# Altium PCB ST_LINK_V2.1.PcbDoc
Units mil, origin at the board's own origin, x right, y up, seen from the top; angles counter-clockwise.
Board outline 1520 x 655 mil, 2 copper layers (Top Layer, Bottom Layer); 55 components, 47 nets, 188 pads, 66 vias.
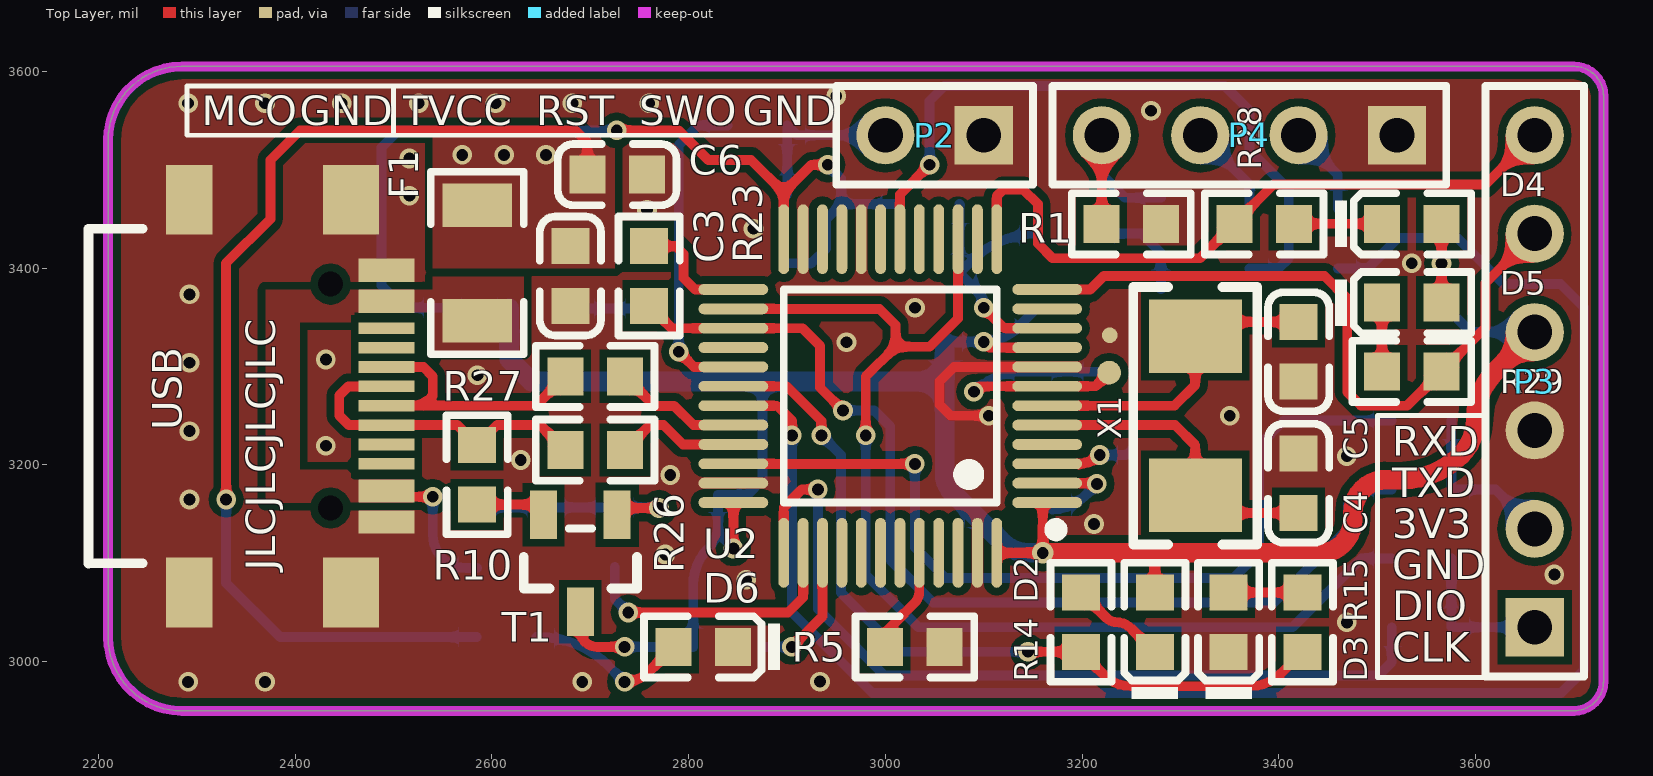
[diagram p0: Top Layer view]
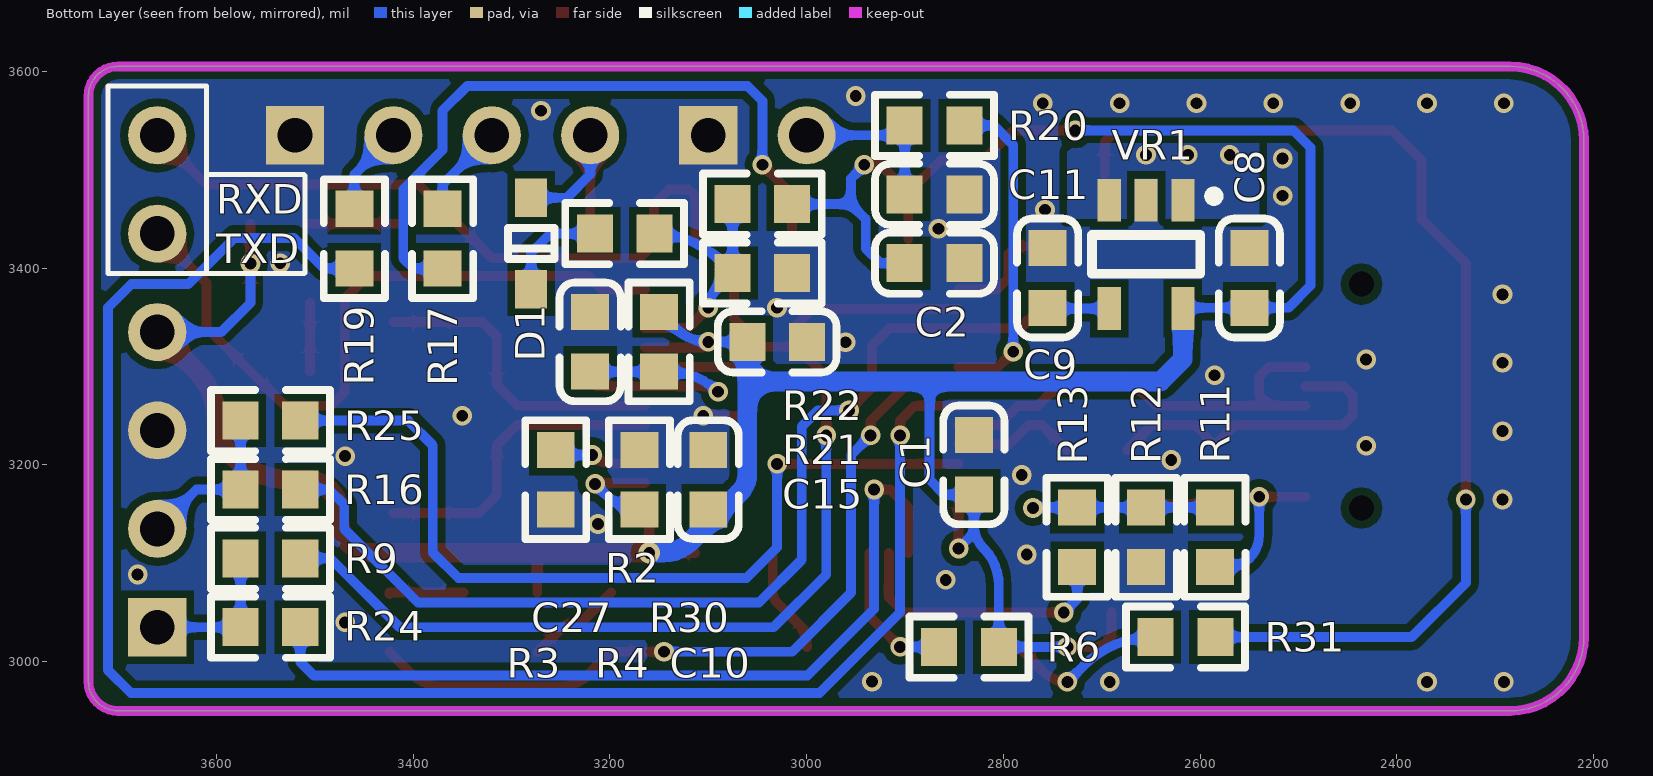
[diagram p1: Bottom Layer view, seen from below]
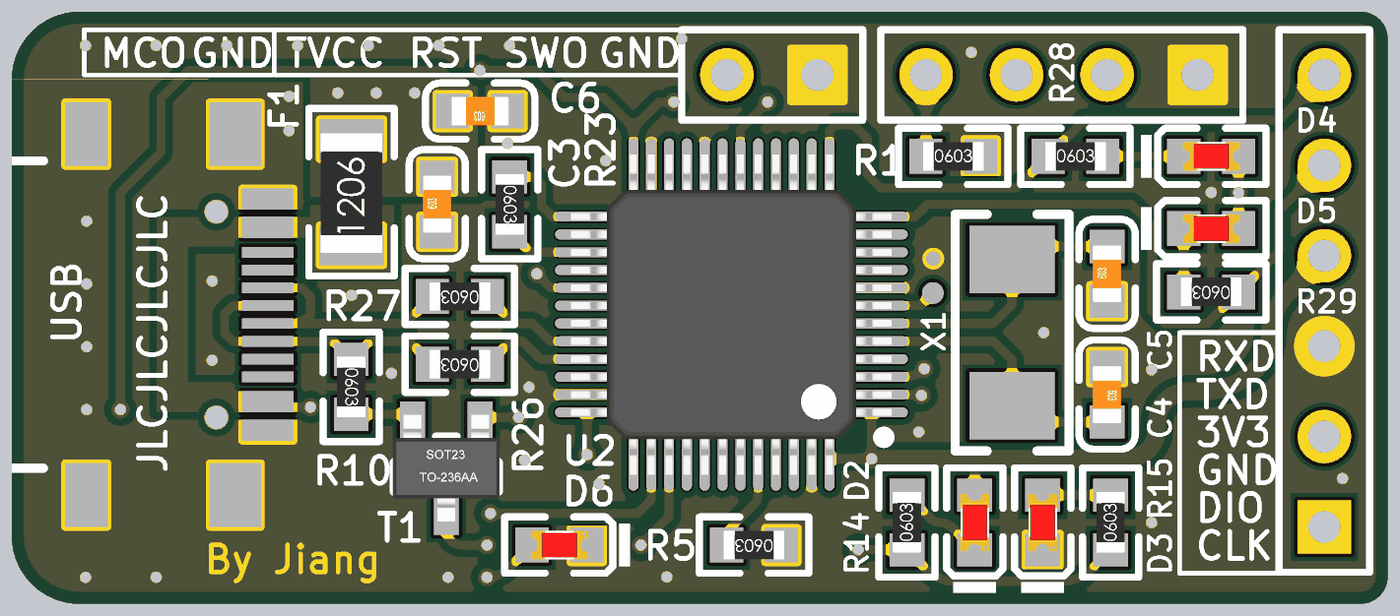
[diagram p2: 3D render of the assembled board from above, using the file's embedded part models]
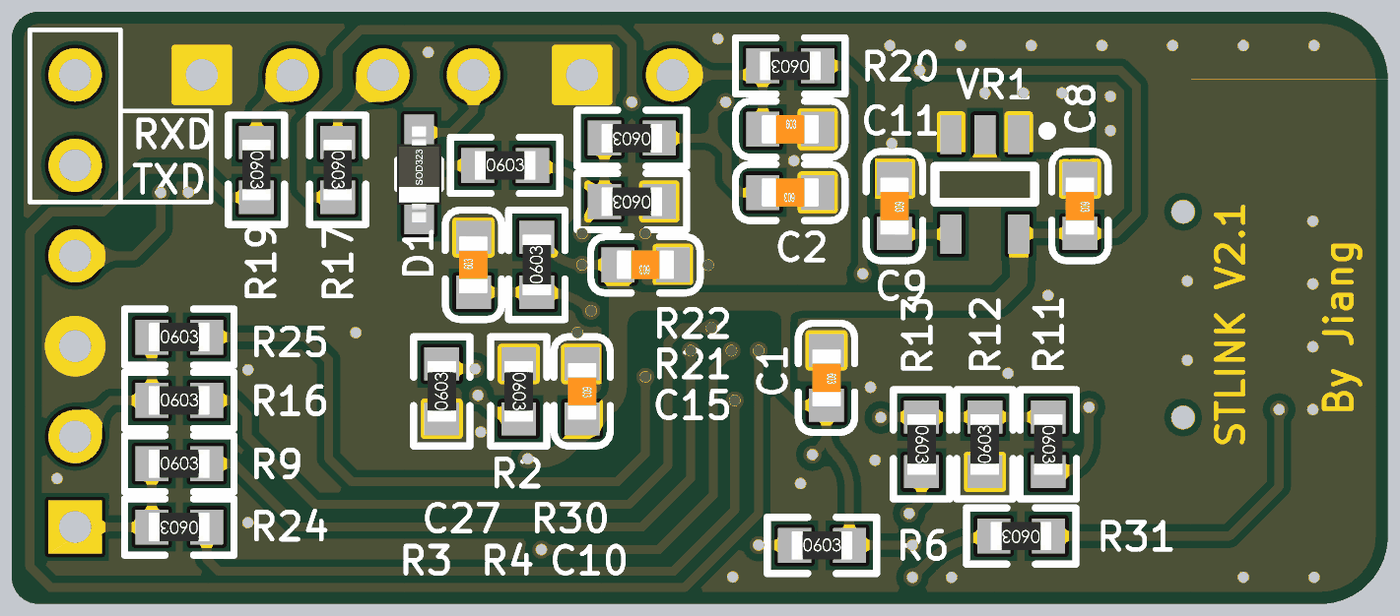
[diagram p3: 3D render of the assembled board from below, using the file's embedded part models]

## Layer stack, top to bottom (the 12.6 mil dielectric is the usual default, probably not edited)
Top Solder: solder mask 0.4, Solder Resist, Dk 3.5
Top Layer: signal copper 1.4
Dielectric 1: dielectric 12.6, FR-4, Dk 4.8
Bottom Layer: signal copper 1.4
Bottom Solder: solder mask 0.4, Solder Resist, Dk 3.5

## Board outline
2285,2950 cw(c2285,3025) 2210,3025 2210,3530 cw(c2285,3530) 2285,3605 3700,3605 cw(c3700,3575) 3730,3575 3730,2980 cw(c3700,2980) 3700,2950

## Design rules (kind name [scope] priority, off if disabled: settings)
Clearance [All] p1: gap=8 ignorepadtopadclearanceinfootprint=TRUE except(0: Arc-Hole Track-Hole SMDPad-Hole THPad-Hole Via-Hole Fill-Hole Poly-Hole Region-Hole Text-Hole)
PolygonConnect PolygonConnect_8 [All vs IsNamedPolygon('Top Layer-5V_USB_CHG 1') Or  IsNamedPolygon('Top Layer-5V_USB_CHG') Or  IsNamedPolygon('Bottom Layer-5V_USB_CHG') Or  IsNamedPolygon('Bottom Layer-GND') Or  IsNamedPolygon('Top Layer-GND') Or  IsNamedPolygon('Top Layer-5V_USB_CHG 2')] p1: connectstyle=Direct reliefconductorwidth=10 reliefentries=4 polygonreliefangle="90 Angle" airgapwidth=10
PolygonConnect PolygonConnect_7 [All vs IsNamedPolygon('Top Layer-5V_USB_CHG 2')] p2: connectstyle=Direct reliefconductorwidth=10 reliefentries=4 polygonreliefangle="90 Angle" airgapwidth=10
PolygonConnect PolygonConnect_6 [All vs IsNamedPolygon('Top Layer-5V_USB_CHG 1')] p3: connectstyle=Direct reliefconductorwidth=10 reliefentries=4 polygonreliefangle="90 Angle" airgapwidth=10
PolygonConnect PolygonConnect_5 [All vs IsNamedPolygon('Top Layer-No Net') Or  IsNamedPolygon('Top Layer-5V_USB_CHG') Or  IsNamedPolygon('Bottom Layer-No Net') Or  IsNamedPolygon('Bottom Layer-5V_USB_CHG') Or  IsNamedPolygon('Top Layer-5V_USB_CHG 2')] p4: connectstyle=Direct reliefconductorwidth=10 reliefentries=4 polygonreliefangle="90 Angle" airgapwidth=10
PolygonConnect PolygonConnect_4 [All vs IsNamedPolygon('Top Layer-5V_USB_CHG 2')] p5: connectstyle=Direct reliefconductorwidth=10 reliefentries=4 polygonreliefangle="90 Angle" airgapwidth=10
PolygonConnect PolygonConnect_3 [All vs IsNamedPolygon('Top Layer-5V_USB_CHG 1') Or  IsNamedPolygon('Top Layer-5V_USB_CHG') Or  IsNamedPolygon('Bottom Layer-5V_USB_CHG')] p6: connectstyle=Direct reliefconductorwidth=10 reliefentries=4 polygonreliefangle="90 Angle" airgapwidth=10
PolygonConnect PolygonConnect_2 [All vs IsNamedPolygon('Top Layer-5V_USB_CHG') Or  IsNamedPolygon('Top Layer-5V_USB_CHG 1')] p7: connectstyle=Direct reliefconductorwidth=10 reliefentries=4 polygonreliefangle="90 Angle" airgapwidth=10
PolygonConnect PolygonConnect_1 [All vs IsNamedPolygon('Top Layer-5V_USB_CHG 1') Or  IsNamedPolygon('Top Layer-5V_USB_CHG')] p8: connectstyle=Direct reliefconductorwidth=10 reliefentries=4 polygonreliefangle="90 Angle" airgapwidth=10
PolygonConnect [All] p9: connectstyle=Relief reliefconductorwidth=10 reliefentries=4 polygonreliefangle="90 Angle" airgapwidth=10
RoutingVias [All] p1: holewidth=12 width=20 viastyle="Through Hole" minholewidth=12 minwidth=18 maxholewidth=28 maxwidth=50
SilkToSilkClearance [All] p1: silktosilkclearance=5
SilkToSolderMaskClearance [IsPad] p1: minsilkscreentomaskgap=5 clearancetoexposedcopper=TRUE
SolderMaskExpansion [All] p1: expansion=4
Width [All] p1: maxlimit=50 minlimit=10 preferedwidth=10
28 further rules are at their usual default settings.

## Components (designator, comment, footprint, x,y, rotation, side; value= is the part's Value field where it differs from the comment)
C1 "Capacitor" 0603_C 2830,3200 r270 bottom value=100nF
C2 "Capacitor" 0603_C 2870,3405 r0 bottom value=100nF
C3 "104" 0603_C 2679.96,3391.97 r90 top
C4 "Capacitor" 0603_C 3420,3181.42 r270 top value=20pF
C5 "Capacitor" 0603_C 3420,3315 r90 top value=20pF
C6 "104" 0603_C 2727.4,3495 r180 top
C8 "104" 0603_C 2550,3390 r270 bottom
C9 "104" 0603_C 2755,3390 r270 bottom
C10 "Capacitor" 0603_C 3100,3185 r270 bottom value=100nF
C11 "20pF" 0603_C 2870,3475 r180 bottom
C15 "Capacitor" 0603_C 3030,3325 r0 bottom value=100nF
C27 "Capacitor" 0603_C 3220,3325 r90 bottom value=103
D1 "BAT60JFILM" SOD-323 3280,3425 r90 bottom
D2 "绿灯 0603" 0603_LED_S1 3273.86,3040 r90 top
D3 "红灯 0603" 0603_LED_S1 3348.86,3040 r90 top
D4 "红灯 0603" 0603_LED_S1 3535,3445 r0 top
D5 "红灯 0603" 0603_LED_S1 3535,3365 r0 top
D6 "红灯 0603" 0603_LED_S1 2815,3015 r180 top
F1 "Fuse 2" 1206_R 2585.31,3405.22 r90 top
P2 "Header 2" HDR1X2 3100,3535 r180 top
P3 "Header 6" HDR1X6 3660,3035 r90 top
P4 "Header 4" HDR1X4 3520,3535 r180 top
R1 "Resistor" 0603_R 3250,3445 r0 top value=10K
R2 "100R" 0603_R 3185,3435 r180 bottom value=22R
R3 "N/A" 0603_R 3255,3185 r90 bottom value=10K
R4 "Resistor" 0603_R 3170,3185 r270 bottom value=10K
R5 "Resistor" 0603_R 3030,3015 r180 top value=100K
R6 "Resistor" 0603_R 2835,3014.69 r180 bottom value=4.7K
R9 "Resistor" 0603_R 3545,3105 r180 bottom value=22R
R10 "Resistor" 0603_R 2585,3190 r270 top value=1K5
R11 "Resistor" 0603_R 2585,3126.42 r270 bottom value=10K
R12 "Resistor" 0603_R 2655,3126.42 r90 bottom value=36K
R13 "Resistor" 0603_R 2725,3126.42 r270 bottom value=100R
R14 "Resistor" 0603_R 3198.86,3040 r90 top value=330R
R15 "Resistor" 0603_R 3423.86,3040 r90 top value=330R
R16 "Resistor" 0603_R 3545,3175 r180 bottom value=22R
R17 "Resistor" 0603_R 3370,3430 r270 bottom value=22R
R19 "Resistor" 0603_R 3459.74,3430 r270 bottom value=22R
R20 "Resistor" 0603_R 2870,3545 r0 bottom value=100R
R21 "Resistor" 0603_R 3045,3395 r0 bottom value=4K7
R22 "Resistor" 0603_R 3045,3465 r0 bottom value=4K7
R23 "Resistor" 0603_R 2760,3391.97 r270 top value=100R
R24 "Resistor" 0603_R 3545,3035 r0 bottom value=0R
R25 "Resistor" 0603_R 3545,3245 r180 bottom value=0R
R26 "Resistor" 0603_R 2705,3215 r180 top value=10R
R27 "Resistor" 0603_R 2705,3290 r180 top value=10R
R28 "Resistor" 0603_R 3385,3445 r0 top value=1K
R29 "Resistor" 0603_R 3535,3295 r180 top value=1K
R30 "Resistor" 0603_R 3150,3325 r90 bottom value=10K
R31 "Resistor" 0603_R 2615,3025 r0 bottom value=1K
T1 "9013-SOT23" SOT-23(SOT-23-3) 2690,3100 r90 top
U2 "STM32F103CBT6" LQFP-48_7x7x05P 3005,3270 r90 top locked
USB "TYPE-C 12P" "TYPE-C 12P 贴片" 2190,3440 r270 top locked
VR1 "SPX3819M5-L-3-3" SOT-23-5 2655,3414.02 r90 bottom
X1 "XTAL_8M_NX3225GD" SMD-5032_2P 3315,3250 r90 top value=8.00Mhz

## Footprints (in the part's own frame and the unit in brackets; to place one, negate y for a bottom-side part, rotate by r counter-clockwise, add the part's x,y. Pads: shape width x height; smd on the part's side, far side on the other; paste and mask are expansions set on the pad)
0603_C [mm]
  rect 0.93x0.98 smd: 1(-0.77,0) 2(0.77,0)
  silkscreen extent -1.53,-0.79 1.54,0.79, body extent -0.8,-0.4 0.8,0.4, height 0.3
0603_LED_S1 [mm]
  rect 0.93x0.98 smd: A(0.77,0) K(-0.77,0)
  silkscreen extent -1.98,-0.79 1.54,0.79, body extent -0.8,-0.4 0.8,0.4, height 0.6
0603_R [mm]
  rect 0.93x0.98 smd: 1(-0.77,0) 2(0.77,0)
  silkscreen extent -1.53,-0.79 1.54,0.79, body extent -0.85,-0.4 0.85,0.4, height 0.56
1206_R [mm]
  rect 1.13x1.8 smd: 1(-1.49,0) 2(1.49,0)
  silkscreen extent -2.36,-1.2 2.35,1.2, body extent -1.7,-0.86 1.65,0.87, height 0.85
HDR1X2 [mm] "Connector; Header; 2 Position"
  rect 1.5x1.5 hole 0.9: 1(0,0)
  round 1.5 hole 0.9: 2(2.54,0)
  silkscreen extent -1.27,-1.27 3.81,1.27
HDR1X4 [mm] "Connector; Header; 4 Position"
  rect 1.5x1.5 hole 0.9: 1(0,0)
  round 1.5 hole 0.9: 2(2.54,0) 3(5.08,0) 4(7.62,0)
  silkscreen extent -1.27,-1.27 8.89,1.27
HDR1X6 [mm] "Connector; Header; 6 Position"
  rect 1.5x1.5 hole 0.9: 1(0,0)
  round 1.5 hole 0.9: 2(2.54,0) 3(5.08,0) 4(7.62,0) 5(10.16,0) 6(12.7,0)
  silkscreen extent -1.27,-1.27 13.97,1.27
LQFP-48_7x7x05P [mm]
  oval 0.28x1.8 smd mask+0.051: 1(-2.75,-4.05) 2(-2.25,-4.05) 3(-1.75,-4.05) 4(-1.25,-4.05) 5(-0.75,-4.05) 6(-0.25,-4.05) 7(0.25,-4.05) 8(0.75,-4.05) 9(1.25,-4.05) 10(1.75,-4.05) 11(2.25,-4.05) 12(2.75,-4.05) 25(2.75,4.05) 26(2.25,4.05) 27(1.75,4.05) 28(1.25,4.05) 29(0.75,4.05) 30(0.25,4.05) 31(-0.25,4.05) 32(-0.75,4.05) 33(-1.25,4.05) 34(-1.75,4.05) 35(-2.25,4.05) 36(-2.75,4.05)
  oval 1.8x0.28 smd mask+0.051: 13(4.05,-2.75) 14(4.05,-2.25) 15(4.05,-1.75) 16(4.05,-1.25) 17(4.05,-0.75) 18(4.05,-0.25) 19(4.05,0.25) 20(4.05,0.75) 21(4.05,1.25) 22(4.05,1.75) 23(4.05,2.25) 24(4.05,2.75) 37(-4.05,2.75) 38(-4.05,2.25) 39(-4.05,1.75) 40(-4.05,1.25) 41(-4.05,0.75) 42(-4.05,0.25) 43(-4.05,-0.25) 44(-4.05,-0.75) 45(-4.05,-1.25) 46(-4.05,-1.75) 47(-4.05,-2.25) 48(-4.05,-2.75)
  silkscreen extent -3.6,-4.42 2.75,2.75, body extent -4.5,-4.5 4.5,4.5, height 1.6
SMD-5032_2P [mm]
  rect 1.9x2.4 smd: 1(-2.05,0) 2(2.05,0)
  silkscreen extent -3.32,-1.6 3.32,1.6
SOD-323 [mm]
  rect 1x0.83 smd: 1(1.18,0) 2(-1.18,0)
  silkscreen extent -0.4,-0.6 0.4,0.6, body extent -1.35,-0.63 1.35,0.63, height 1.1
SOT-23(SOT-23-3) [mm]
  rect 1.25x0.7 smd: 1(1.25,-0.95) 2(1.25,0.95) 3(-1.25,0)
  silkscreen extent -0.65,-1.46 0.9,1.46, body extent -1.5,-1.5 1.5,1.5, height 1.3
SOT-23-5 [mm]
  rect 1.1x0.6 smd: 1(1.4,-0.95) 2(1.4,0) 3(1.4,0.95) 4(-1.4,0.95) 5(-1.4,-0.95)
  silkscreen extent -0.5,-1.87 1.62,1.4
"TYPE-C 12P 贴片" [mm]
  rect 1.8x1.45 smd: 0(-0.75,6.78) 0(9.39,6.78)
  rect 1.8x1.2 smd: 0(-0.75,2.6) 0(9.39,2.6)
  round 0 hole 0.65: 5(1.43,6.25) 5(7.21,6.25)
  rect 0.3x1.45 smd: A1(0.92,7.695) A4(1.72,7.695) A5(3.07,7.695) A6(4.07,7.695) A7(4.57,7.695) A8(5.57,7.695) A9(6.92,7.695) A12(7.72,7.695) B1(7.42,7.695) B4(6.62,7.695) B5(6.07,7.695) B6(5.07,7.695) B7(3.57,7.695) B8(2.57,7.695) B9(2.02,7.695) B12(1.22,7.695)
  silkscreen extent 0,0 8.64,1.4, body extent 0,0 8.64,8, height 3.21

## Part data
C1 C2 C10 C15 C27: library part MCD-00211, "Capacitor, MLCC, 100nF, 16V, X7R, 10%, 0603, T=0,8mm", Manufacturer=YAGEO, Manufacturer_Part_Number=CC0603KRX7R7BB104, Package=C0603
C3 C6 C8 C9: library part "0603 2.7pF (2R7) 0.25pF 50V", "贴片电容", Package=0603, SuppliersPartNumber=C16149
C4 C5: library part MCD-00637, "Capacitor, MLCC, 10pF, 50V, NPO, 5%, 0603, T=0,8mm", Manufacturer=YAGEO, Manufacturer_Part_Number=CC0603JRNPO9BN100, Package=C0603
C11: library part MCD-00638, "Capacitor, MLCC, 20pF, 50V, NPO, 5%, 0603, T=0,8mm", Manufacturer=YAGEO, Manufacturer_Part_Number=CC0603JRNPO9BN200, Package=C0603
D1: library part MCD-00034, Manufacturer=STMICROELECTRONICS
D2: library part "0603 绿灯", "发光二极管", Package=0603, SuppliersPartNumber=C72043
D3 D4 D5 D6: library part "0603 红灯", "发光二极管", Package=0603, SuppliersPartNumber=C2286
F1: "Fuse"
P2: "Header, 2-Pin"
P3: "Header, 6-Pin"
P4: "Header, 4-Pin"
R1 R3 R4 R11: library part MCD-00220, "Resistor,10K,0603,1%,1/10W", Manufacturer=YAGEO, Manufacturer_Part_Number=RC0603FR-0710KL, Package=R0603
R2 R9 R16 R17 R19 R24 R25: library part MCD-00066, "Resistor,22R,0603,1%,1/10W", Manufacturer=YAGEO, Manufacturer_Part_Number=RC0603FR-0722RL, Package=R0603
R5 R30: library part MCD-00223, "Resistor,100K,0603,1%,1/10W", Manufacturer=YAGEO, Manufacturer_Part_Number=RC0603FR-07100KL, Package=R0603
R6 R14 R15 R28 R29 R31: library part MCD-00197, "Resistor,330R,0603,1%,1/10W", Manufacturer=YAGEO, Manufacturer_Part_Number=RC0603FR-07330RL, Package=R0603
R10: library part MCD-00217, "Resistor,1K5,0603,1%,1/10W", Manufacturer=YAGEO, Manufacturer_Part_Number=RC0603FR-071K5L, Package=R0603
R12: library part MCD-00221, "Resistor,36K,0603,1%,1/10W", Manufacturer=YAGEO, Manufacturer_Part_Number=RC0603FR-0736KL, Package=R0603
R13 R20 R23 R26 R27: library part MCD-00224, "Resistor,100R,0603,1%,1/10W", Manufacturer=YAGEO, Manufacturer_Part_Number=RC0603FR-07100RL, Package=R0603
R21 R22: library part MCD-00219, "Resistor,4K7,0603,1%,1/10W", Manufacturer=YAGEO, Manufacturer_Part_Number=RC0603FR-074K7L, Package=R0603
T1: library part MCD-00073, "NPN Bipolar Transistor", Manufacturer=NXP, Manufacturer_Part_Number=BSR14
U2: library part MCD-00085, "Medium-density performance line ARM-based 32-bit MCU with 128KB Flash", Manufacturer=STMICROELECTRONICS
VR1: "LDO"
X1: library part MCD-00092, "Crystal 8Mhz, 8pF, -+50PPM, SMD", Manufacturer=NDK, Manufacturer_Part_Number="NX3225GD 8MHz EXS00A-CG04874"

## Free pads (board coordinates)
  round 24 smd: 9(3227.46,3293.78)
  round 16 smd: 10(3227.98,3331.84)

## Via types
v1: diameter 20, hole 12, Top Layer to Bottom Layer, tented both sides, 65 vias
v2: diameter 22, hole 12, Top Layer to Bottom Layer, tented both sides, 1 vias

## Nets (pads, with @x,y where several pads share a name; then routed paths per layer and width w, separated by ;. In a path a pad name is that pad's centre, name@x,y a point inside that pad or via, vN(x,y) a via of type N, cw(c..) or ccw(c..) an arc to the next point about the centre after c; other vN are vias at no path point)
3V3_STLK: C1.2 C2.2 C8.2 C10.2 C15.2 D2.A D4.A D5.A P3.4 R6.2 R22.1 R30.2 T1.3 U2.1 U2.9 U2.24 U2.36 U2.48 VR1.5 | length 3500
  Top Layer w10: T1.3 2690,3032.07 ccw(c2707.07,3032.07) 2695,3020 ccw(c2707.07,3032.07) 2707.07,3015 v1(2735,3015) ; v1(2727,3540) 2790,3540 2820,3510 2863.46,3510 2896.73,3476.73 ; v1(2845.55,3115.08) U2.36 ; U2.24 2896.73,3476.73 ; v1(2941.37,3505) 2925,3505 2896.73,3476.73 ; v1(3100,3325) 3105.79,3319.21 U2.9 ; U2.48 v2(3160,3110.55) 3160,3161.73 U2.1 ; D2.A 3273.86,3110.55 ; D5.A v1(3565.31,3404.69) D4.A
  Top Layer w20: v2(3160,3110.55) 3273.86,3110.55 3442.19,3110.55 ccw(c3442.19,3142.81) 3465,3120 ccw(c3440.86,3144.14) 3475,3144.14 3475,3150.86 cw(c3509.14,3150.86) 3485,3175 cw(c3509.14,3150.86) 3509.14,3185 3524.64,3185 ccw(c3524.64,3270.36) 3585,3210 ccw(c3548.79,3246.21) 3600,3246.21 cw(c3669.5,3246.21) 3620.36,3295.36 P3.4
  Bottom Layer w10: VR1.5 ccw(c2615.7,3357) 2615.7,3359.69 C8.2 2510.39,3359.69 2487.75,3382.32 2487.75,3522.68 2505.07,3540 v1(2727,3540) ; v1(2735,3015) 2804.37,3015 R6.2 2804.68,3078.03 cw(c2856.97,3078.03) 2820,3115 ccw(c2795.86,3139.14) 2830,3139.14 ; v1(2845.55,3115.08) 2836.02,3124.61 cw(c2850.55,3139.14) 2830,3139.14 ; 2875,3284.69 2875,3185 2859.69,3169.69 C1.2 2830,3139.14 ; C2.2 2925,3405 2940,3420 2940,3450 2955,3465 ; v1(2941.37,3505) 2941.37,3504.7 2955,3491.07 2955,3465 ; R22.1 2955,3465 ; C15.2 v1(3100,3325) ccw(c3100,3372.52) 3133.6,3338.92 R30.2 ; v1(3565.31,3404.69) 3565.31,3364.69 3595,3335 P3.4
  Bottom Layer w20: VR1.5 2617.6,3307.4 2640.31,3284.69 2875,3284.69 3060.31,3284.69 ; C15.2 3060.31,3284.69 ; 3068.5,3171.19 cw(c3088.25,3190.94) 3060.31,3190.94 3060.31,3284.69 ; 3068.5,3171.56 3117.65,3122.41 ccw(c3146.28,3151.04) 3146.28,3110.55 v2(3160,3110.55)
5V_USB_CHG: F1.1 R11.2 USB.A4 USB.A9 USB.B4 USB.B9 | length 149.9
  Top Layer w10: USB.A9 v1(2540,3167.56)
  Bottom Layer w10: v1(2540,3167.56) 2540,3129.14 ccw(c2574.14,3129.14) 2550,3105 ccw(c2573.76,3128.76) 2573.76,3095.16 R11.2@2585,3095.16
AIN_1: R2.2 R21.2 R22.2 U2.10 | length 280.3
  Top Layer w10: v1(3100,3359.68) 3120.79,3338.9 U2.10
  Bottom Layer w10: R22.2@3076.03,3464.29 R22.2 R21.2 ; v1(3100,3359.68) ccw(c3074.34,3359.68) 3092.48,3377.83 R21.2 ; R2.2 ccw(c3154.68,3339.95) 3087.48,3407.16 R21.2
GND: C1.1 C2.1 C3.1 C4.1 C5.1 C6.1 C8.1 C9.1 C10.1 C11.2 C15.1 C27.2 D3.K D6.K P2.1 P3.3 P4.1 pad.10 R1.2 R3.1 R4.1 R5.1 R12.1 R21.1 U2.8 U2.20 U2.23 U2.35 U2.47 USB.0 USB.A1 USB.A12 USB.B1 USB.B12 VR1.2 | length 193.7
  Top Layer w10: v1(3105,3250) 3066.21,3250 3055,3261.21 3055,3284.69 3069.84,3299.53 U2.8
  other v1: 2291.36,2979.43 2369.47,2979.43 2691.89,2979.43 2933.61,2979.69 3469.11,3039.9 2858.65,3083.1 3680,3088.58 2776.36,3108.9 3212,3140 2292.72,3164.85 2781.36,3189.69 2629.48,3204.97 3469.11,3208.9 2431.36,3219.42 2292.72,3234.33 3350,3250 2585.31,3291.19 2292.72,3303.81 2431.36,3307.09 2960.57,3324.69 3030.19,3359.68 2292.72,3373.29 3535,3405 2865.99,3440.02 2757.72,3459.37 2516.26,3473.46 2516.26,3511.32 3270,3560 2291.36,3567.47 2369.47,3567.47 2447.57,3567.47 2525.68,3567.47 2603.79,3567.47 2681.89,3567.47 2760,3567.47 2950,3575
LED_STLK: R14.1 R15.1 U2.30 | length 806
  Top Layer w10: U2.30 2899.84,3279.84 2935,3244.69 v1(2935,3230) ; v1(3145,3010) 3198.54,3010 R14.1 3222.21,2986.34 ccw(c3249.58,3013.71) 3249.58,2975 3370.86,2975 ccw(c3370.86,3019.22) 3402.12,2987.95 R15.1
  Bottom Layer w10: v1(2935,3230) 2955,3210 2955,3070 3015,3010 v1(3145,3010)
MCO: C11.1 P2.2 R20.2 | length 173.8
  Bottom Layer w10: C11.1 R20.2 2910.32,3535 P2.2
NetC3_2: C3.2 C6.2 F1.2 R31.1 VR1.1 VR1.3 | length 1098.5
  Top Layer w10: v1(2330,3164.85) 2330,3405 2375,3450 2375,3510 2405,3540 2685,3540 2697.09,3527.91 C6.2
  Bottom Layer w10: v1(2330,3164.85) 2330,3080 2385,3025 R31.1
  other v1: 2570,3515.07 2612.5,3515.07 2655,3515.07
NetC9_2: C9.2 VR1.4 | length 62.8
  Bottom Layer w10: VR1.4 2753.1,3358.9 ccw(c2753.1,3361.59) C9.2
NetD1_2: D1.2 R2.1 | length 109.6
  Bottom Layer w10: R2.1 3260.31,3435 3280,3415.32 D1.2
NetD2_K: D2.K R14.2 | length 98.6
  Top Layer w10: R14.2 3225.05,3044.12 ccw(c3235,3054.07) 3235,3040 cw(c3235,3019.37) 3249.58,3033.97 D2.K
NetD3_A: D3.A R15.2 | length 76.5
  Top Layer w10: D3.A R15.2 R15.2@3423.86,3068.86
NetD4_K: D4.K R28.2 | length 89.4
  Top Layer w10: R28.2 D4.K
NetD5_K: D5.K R29.2 | length 70
  Top Layer w10: R29.2 D5.K
NetD6_A: D6.A R31.2 | length 167.2
  Top Layer w10: v1(2735,2979.43) ccw(c2735,3013.51) 2759.1,2989.41 D6.A
  Bottom Layer w10: R31.2 2648.01,3025 cw(c2648.01,2925) 2718.72,2995.71 v1(2735,2979.43)
NetP3_1: P3.1 R9.1 R24.2 | length 154.7
  Bottom Layer w10: R9.1 R24.2 P3.1
NetP3_2: P3.2 R16.1 R25.1 | length 171.3
  Bottom Layer w10: R25.1 R16.1 3620,3175 P3.2
NetP4_2: P4.2 R19.1 | length 91.1
  Bottom Layer w10: P4.2 3459.74,3495.26 R19.1
NetP4_3: P4.3 R17.1 | length 95.4
  Bottom Layer w10: P4.3 3370,3485 R17.1
NetR3_2: R3.2 U2.3 | length 90.1
  Top Layer w10: U2.3 3196.52,3201.1 ccw(c3196.52,3231.48) v1(3218,3210)
  Bottom Layer w10: v1(3218,3210) 3244.68,3210 R3.2@3250,3215.32
NetR4_2: R4.2 U2.2 | length 104.5
  Top Layer w10: U2.2 3213.29,3181.42 cw(c3213.29,3179) v1(3215,3180.71)
  Bottom Layer w10: R4.2 ccw(c3170,3200.5) 3202.39,3168.1 v1(3215,3180.71)
NetR5_2: R5.2 U2.44 | length 107.8
  Top Layer w10: R5.2 cw(c3035.14,3015) 3010.07,3040.07 3030,3060 ccw(c3019.07,3070.93) 3034.53,3070.93 U2.44
NetR6_1: R6.1 U2.39 | length 133.4
  Top Layer w10: v1(2905,3015) 2936.1,3046.1 U2.39
  Bottom Layer w10: R6.1@2880.31,3015 2880.63,3014.69 2880.94,3015 v1(2905,3015)
NetR10_2: R10.2 T1.2 | length 71.9
  Top Layer w10: R10.2 2642.13,3159.68 T1.2
NetR11_1: R11.1 R12.2 R13.1 T1.1 | length 231
  Top Layer w10: T1.1 2734.33,3156.14 v1(2770,3156.14)
  Bottom Layer w10: R11.1 R12.2 R13.1 2768.7,3156.73 2769.65,3155.79 v1(2770,3156.14)
NetR20_1: R20.1 U2.29 | length 330.1
  Top Layer w10: v1(2790,3315) 2805.47,3299.53 U2.29
  Bottom Layer w10: v1(2790,3315) 2790,3525.32 2809.68,3545 R20.1
NetR26_1: R26.1 U2.33 | length 128.9
  Top Layer w10: R26.1 2760.79,3240.47 2774.53,3240.47 2794.21,3220.79 U2.33
NetR27_1: R27.1 U2.32 | length 130.8
  Top Layer w10: R27.1 2765.31,3260 2785.46,3260 2804.98,3240.47 U2.32
OSC_IN: C4.2 U2.5 X1.1 | length 322.3
  Top Layer w10: U2.5 3294.53,3240.47 3315,3220 X1.1 3333.19,3151.1 C4.2
OSC_OUT: C5.2 U2.6 X1.2 | length 319.9
  Top Layer w10: U2.6 3294.02,3260.16 3315,3281.14 X1.2 3329.61,3345.31 C5.2
PWR_ENn: U2.28
STL_USB_D_N: R27.2 USB.A7 USB.B7 | length 279.1
  Top Layer w10: USB.A7 2530.08,3260.08 ; USB.B7 2530.55,3299.45 2540,3290 2540,3270 2530.08,3260.08 ; R27.2 2644.76,3260.08 2530.08,3260.08
STL_USB_D_P: R10.1 R26.2 USB.A6 USB.B6 | length 333.2
  Top Layer w10: USB.A6 2454.13,3279.76 2445,3270.63 2445,3250 2454.61,3240.39 USB.B6 2564.92,3240.39 R10.1 2585.31,3220.31 2605.47,3240.47 2649.21,3240.47 R26.2
STLK_RX: P3.6 R28.1 U2.13 | length 697.5
  Top Layer w10: U2.13 3113.27,3473.27 3120,3480 3140,3480 3155,3465 3155,3425 3170,3410 3319.69,3410 R28.1 3394.69,3485 3610,3485 P3.6
STLK_TX: P3.5 R29.1 U2.12 | length 710.2
  Top Layer w10: U2.12 3208.27,3378.27 3221.97,3391.97 3446.3,3391.97 3469.46,3368.8 3469.46,3274.24 3483.54,3260.16 3530.47,3260.16 R29.1 3610,3339.69 3610,3385 P3.5
STM_JTCK: R24.1 U2.37 | length 862.1
  Top Layer w10: U2.37 2896.73,3156.73 2915,3175 v1(2931.42,3175)
  Bottom Layer w10: v1(2931.42,3175) 2931.42,3053.58 2999,2986 3501,2986 3514.69,2999.69 R24.1
STM_JTMS: R25.2 U2.34 | length 897
  Top Layer w10: U2.34 2845.63,3201.02 v1(3030,3201.02)
  Bottom Layer w10: v1(3030,3201.02) 3030,3116.1 3061.1,3085 3353.9,3085 3380,3111.1 3380,3220 3405,3245 R25.2
STM_RST: C27.1 pad.9 R30.1 U2.7 | length 280.9
  Top Layer w10: v1(3090,3274.24) 3095.76,3280 U2.7@3164.29,3280 ; U2.7 3213.52,3279.84 pad.9
  Bottom Layer w10: v1(3090,3274.24) cw(c3139.36,3224.88) 3139.36,3294.69 R30.1 C27.1
T_JRST: U2.19
T_JTCK: R9.2 U2.15 U2.26 | length 1179.7
  Top Layer w10: U2.26 2993.92,3358.58 3010.31,3342.19 3010.31,3320 ; v1(2980,3230) 2980,3289.69 3010.31,3320 ; U2.15 3073.9,3348.9 3045,3320 3010.31,3320
  Bottom Layer w10: v1(2980,3230) 2980,3088.58 3033.58,3035 3413.9,3035 3483.9,3105 R9.2
T_JTDI: U2.17
T_JTDO: U2.16
T_JTMS: R16.2 R23.2 U2.27 | length 1047.8
  Top Layer w10: R23.2 2782.76,3338.9 U2.27 2915.79,3338.9 2933.61,3321.08 2933.61,3278.71 v1(2957,3255.31)
  Bottom Layer w10: v1@2955,3255.31 v1(2957,3255.31) 2988.69,3255.31 3005,3239 3005,3103.58 3048.58,3060 3395,3060 3470,3135 3470,3159.57 3485.43,3175 R16.2
T_NRST: R17.2 U2.18 | length 705.5
  Top Layer w10: U2.18 3014.84,3474.84 v1(3045,3505)
  Bottom Layer w10: v1(3045,3505) 3045,3570 3060,3585 3345,3585 3370,3560 3370,3520 3410,3480 3410,3410 3399.68,3399.68 R17.2
T_SWDIO_IN: R23.1 U2.25 | length 118
  Top Layer w10: R23.1 2786.93,3422.28 2795,3414.21 2795,3389.98 2806.72,3378.27 U2.25
T_SWO: R19.2 U2.31 | length 1770.3
  Top Layer w10: U2.31 2889.68,3260.16 2905,3244.84 v1(2905,3230)
  Bottom Layer w10: v1(2905,3230) 2905,3050 2987,2968 3686.75,2968 3710,2991.25 3710,3360 3686.3,3383.7 3628.45,3383.7 3581.54,3430.61 3521.24,3430.61 3490.32,3399.68 R19.2
T_VCC: D1.1 P4.4 R1.1 | length 199.9
  Top Layer w10: R1.1 3220,3445.31 P4.4
  Bottom Layer w10: P4.4 3220,3495 3243.54,3471.46 D1.1
USB_RENUMn: R13.2 U2.38 | length 281.1
  Top Layer w10: v1(2738.74,3050) 2901.14,3050 2916.42,3065.28 U2.38
  Bottom Layer w10: R13.2 2725,3063.74 v1(2738.74,3050)
pads on no net: U2.4 U2.11 U2.14 U2.21 U2.22 U2.40 U2.41 U2.42 U2.43 U2.45 U2.46 USB.5 USB.A5 USB.A8 USB.B5 USB.B8

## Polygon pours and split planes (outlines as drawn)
GND on Top Layer "Top Layer-GND" (solid, pour order 11): 2210,3025 2210,3530 cw(c2285,3530) 2285,3605 3700,3605 cw(c3700,3575) 3730,3575 3730,2980 cw(c3700,2980) 3700,2950 2285,2950 cw(c2285,3025)
NetC3_2 on Top Layer "Top Layer-5V_USB_CHG 2" (solid, pour order 2): 2540,3400 2725,3400 2725,3535 2540,3535
5V_USB_CHG on Top Layer "Top Layer-5V_USB_CHG 1" (solid, pour order 1): 2464.91,3378.09 2540,3378.09 2540,3391.13 2632.5,3391.13 2632.5,3315 2540,3315 2540,3355 2464.91,3355
5V_USB_CHG on Top Layer "Top Layer-5V_USB_CHG" (solid, pour order 0): 2520,3378.06 2370,3378.06 2370,3161.73 2520,3161.73 2520,3185 2460,3185 2460,3195 2405,3195 2405,3345 2460,3345 2460,3355 2520,3355
GND on Bottom Layer "Bottom Layer-GND" (solid, pour order 13): 2210,3025 2210,3530 cw(c2285,3530) 2285,3605 3700,3605 cw(c3700,3575) 3730,3575 3730,2980 cw(c3700,2980) 3700,2950 2285,2950 cw(c2285,3025)
NetC3_2 on Bottom Layer "Bottom Layer-5V_USB_CHG" (solid, pour order 3): 2540,3529.21 2540,3450 2735,3450 2735,3529.21

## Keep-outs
Keep-Out Layer:
  the board outline again, w10

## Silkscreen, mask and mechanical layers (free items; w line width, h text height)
Top Overlay:
  lines w5: 2500,3535 2500,3585 ; 3608.9,2983.9 3500,2983.9 3500,3250 3610,3250 ; 2290,3535 2290,3585 2950,3585 2950,3535 2290,3535
  text "MCO" at 2305,3545 h30
  text "GND" at 2405,3545 h30
  text "TVCC" at 2510,3545 h30
  text "RST" at 2645,3545 h30
  text "SWO" at 2750,3545 h30
  text "GND" at 2855,3545 h30
  text "RXD" at 3515,3209.17 h30
  text "TXD" at 3515,3167.34 h30
  text "3V3" at 3515,3125.5 h30
  text "JLCJLCJLCJLC" at 2380,3092.2 h30 r90
  text "GND" at 3515,3083.67 h30
  text "DIO" at 3515,3041.83 h30
  text "CLK" at 3515,3000 h30
Bottom Overlay:
  lines w5: 3610,3394.67 3610,3495 ; 3610,3495 3610,3585 3710,3585 3710,3394.33 3510.67,3394.33 3510,3395 3510,3494.33 3510.67,3495 3610,3495
  text "RXD" at 3600,3455 h30
  text "TXD" at 3600,3405 h30
Top Solder:
  text "By Jiang" at 2420,2985 h30
Bottom Solder:
  text "By Jiang" at 2250,3155.31 h30 r270
  text "STLINK V2.1" at 2369.47,3120 h30 r270
Mechanical 1:
  lines w5: 2285,3605 ccw(c2285,3530) 2210,3530 2210,3025 ccw(c2285,3025) 2285,2950 3700,2950 ; 2285,3605 3700,3605 ; 2285,3605 2285,3605 ; 3700,2950 ccw(c3700,2980) 3730,2980 3730,3575 ccw(c3700,3575) 3700,3605 ; 3700,2950 3700,2950 ; 3700,3605 3700,3605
